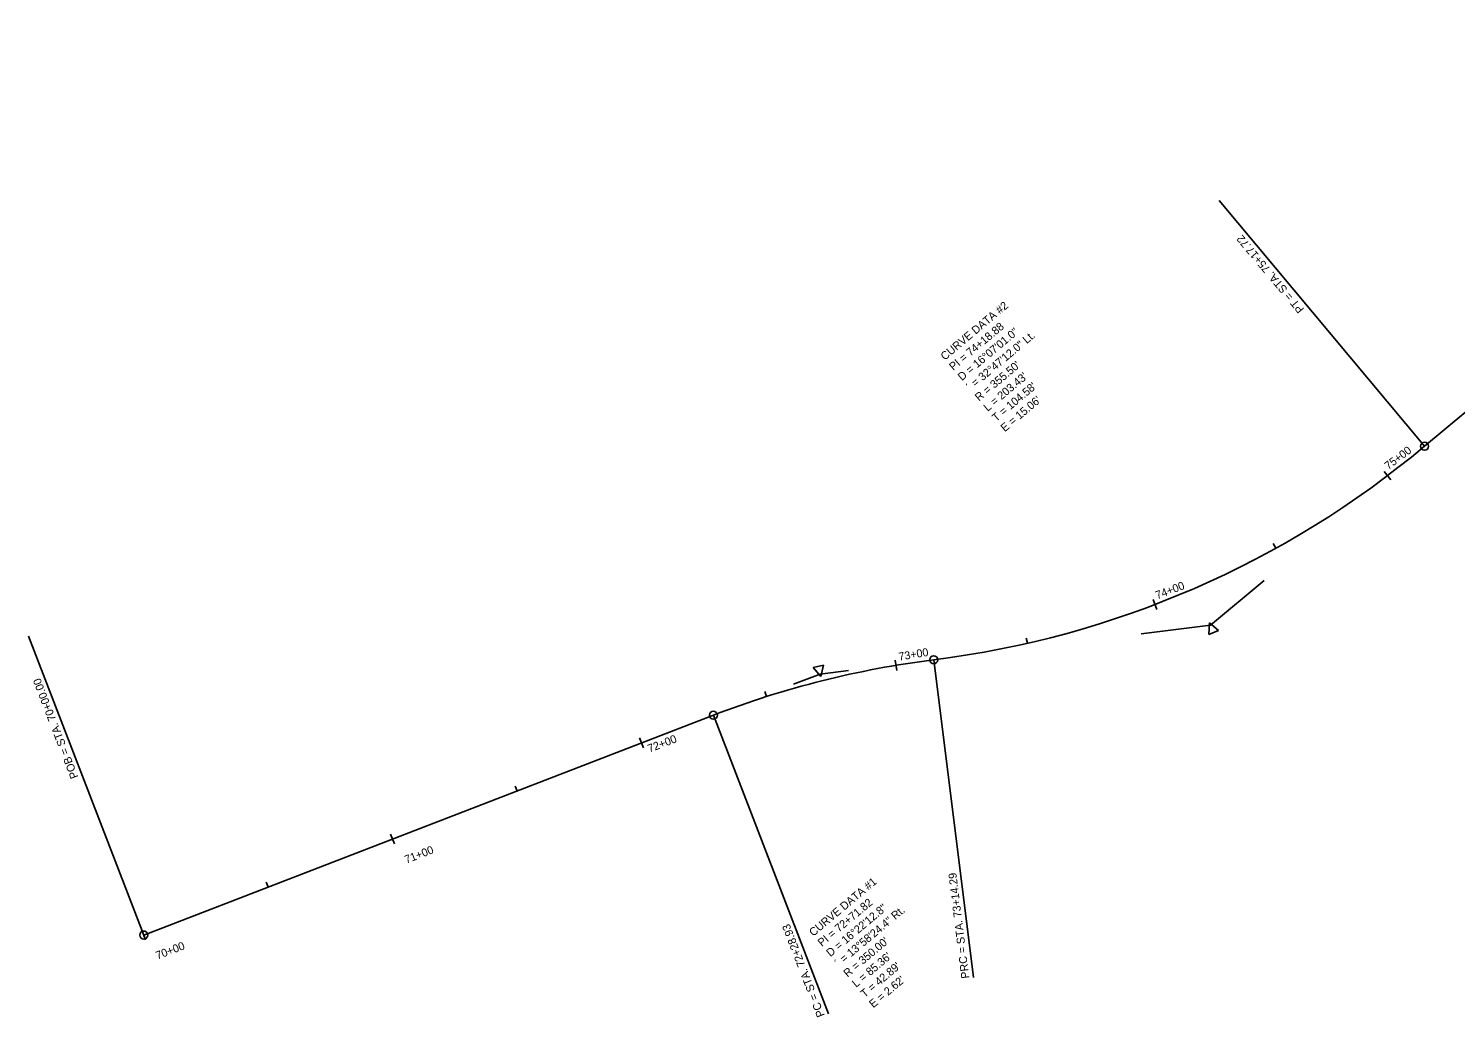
# Model space of a CAD drawing. Extents: x 939026 to 940035, y 627480 to 628252.
# Drawn here: x 939026 to 939561, y 627480 to 627851 of the extents above; entities that cross this region are included whole.
import ezdxf

# ---------------------------------------------------------------- set-up
doc = ezdxf.new("R2010")
doc.units = 0
for name, color, linetype in [('D_Roadway_Centerline', 7, 'Continuous'), ('D_Roadway_Centerline_CurveData', 7, 'Continuous'), ('D_Roadway_Centerline_Flags', 7, 'Continuous'), ('D_Roadway_Centerline_Text', 7, 'Continuous')]:
    doc.layers.add(name, color=color, linetype=linetype)

msp = doc.modelspace()

# ---------------------------------------------------------------- linework, layer by layer
at = {"layer": 'D_Roadway_Centerline'}
for p, q in [((939549.37, 627694.24), (939736.56, 627850.77)), ((939069.18, 627511.07), (939282.77, 627593.45))]:
    msp.add_line(p, q, dxfattribs=at)
for centre, radius, start, end in [((939321.32, 627966.96), 355.5, 277.1159, 309.9025), ((939408.71, 627266.89), 350, 97.1159, 111.0893)]:
    msp.add_arc(centre, radius, start, end, dxfattribs=at)
at = {"layer": 'D_Roadway_Centerline_CurveData'}
for p, q in [((939468.51, 627623.66), (939468.74, 627628.06)), ((939468.74, 627628.06), (939472.12, 627625.23)), ((939468.74, 627628.06), (939469.13, 627627.15)), ((939472.12, 627625.23), (939468.51, 627623.66)), ((939320.17, 627611.27), (939323.98, 627612.23)), ((939323.03, 627607.93), (939320.17, 627611.27)), ((939323.98, 627612.23), (939323.03, 627607.93)), ((939323.03, 627607.93), (939322.79, 627608.88))]:
    msp.add_line(p, q, dxfattribs=at)
for points in [[(939443.19, 627623.91), (939469.13, 627627.15), (939489.19, 627643.92)], [(939312.79, 627605.03), (939322.79, 627608.88), (939333.43, 627610.21)]]:
    msp.add_lwpolyline(points, dxfattribs=at)
at = {"layer": 'D_Roadway_Centerline_Flags'}
for points in [[(939549.37, 627694.24), (939472.39, 627786.3)], [(939069.18, 627511.07), (939026, 627623.04)], [(939365.36, 627614.2), (939380.22, 627495.12)], [(939282.77, 627593.45), (939325.95, 627481.49)]]:
    msp.add_lwpolyline(points, dxfattribs=at)
for centre in [(939549.37, 627694.24), (939365.36, 627614.2), (939282.77, 627593.45), (939069.18, 627511.07)]:
    msp.add_circle(centre, 1.5, dxfattribs=at)
at = {"layer": 'D_Roadway_Centerline_Text'}
for points in [[(939534.29, 627684.81), (939536.7, 627681.62)], [(939492.63, 627657.74), (939493.6, 627656)], [(939447.6, 627636.78), (939449.02, 627633.05)], [(939400.06, 627622.34), (939400.51, 627620.39)], [(939350.89, 627614.11), (939351.54, 627610.16)], [(939302.04, 627602.34), (939302.65, 627600.43)], [(939255.06, 627584.91), (939256.5, 627581.17)], [(939208.41, 627566.91), (939209.13, 627565.05)], [(939161.76, 627548.92), (939163.2, 627545.19)], [(939115.11, 627530.93), (939115.83, 627529.07)], [(939068.46, 627512.94), (939069.9, 627509.21)]]:
    msp.add_lwpolyline(points, dxfattribs=at)

# ---------------------------------------------------------------- texts
at = {"layer": 'D_Roadway_Centerline_CurveData'}
for s, rotation, p in [('CURVE DATA #2', 40.0101, (939369.49, 627726.26)), ('PI = 74+18.88', 40.0101, (939372.7, 627722.43)), ('D = 16%%d07\'01.0"', 40.0101, (939375.92, 627718.6)), ('´ = 32%%d47\'12.0" Lt.', 40.0101, (939379.13, 627714.77)), ("R = 355.50'", 40.0101, (939382.34, 627710.94)), ("L = 203.43'", 40.0101, (939385.56, 627707.11)), ("T = 104.58'", 40.0101, (939388.77, 627703.28)), ("E = 15.06'", 40.0101, (939391.99, 627699.45)), ('CURVE DATA #1', 39.9833, (939320.2, 627510.4)), ('PI = 72+71.82', 39.9833, (939323.41, 627506.57)), ('D = 16%%d22\'12.8"', 39.9833, (939326.62, 627502.74)), ('´ = 13%%d58\'24.4" Rt.', 39.9833, (939329.83, 627498.91)), ("R = 350.00'", 39.9833, (939333.05, 627495.08)), ("L = 85.36'", 39.9833, (939336.26, 627491.25)), ("T = 42.89'", 39.9833, (939339.47, 627487.41)), ("E = 2.62'", 39.9833, (939342.69, 627483.58))]:
    msp.add_text(s, height=3, rotation=rotation, dxfattribs=at).set_placement(p)
at = {"layer": 'D_Roadway_Centerline_Flags'}
for s, rotation, p in [('PT = STA. 75+17.72', 129.9025, (939504.4, 627745.67)), ('POB = STA. 70+00.00', 111.0893, (939044.72, 627570.33)), ('PRC = STA. 73+14.29', 97.1159, (939378.73, 627494.94)), ('PC = STA. 72+28.93', 111.0893, (939324.55, 627480.95))]:
    msp.add_text(s, height=3, rotation=rotation, dxfattribs=at).set_placement(p)
at = {"layer": 'D_Roadway_Centerline_Text'}
for s, rotation, p in [('75+00', 37.0465, (939535.79, 627685.32)), ('74+00', 20.9295, (939449.17, 627636.85)), ('73+00', 9.4554, (939352.45, 627613.86)), ('72+00', 21.0893, (939258.8, 627579.38)), ('71+00', 21.0893, (939167.66, 627537.8)), ('70+00', 21.0893, (939074.35, 627501.82))]:
    msp.add_text(s, height=3, rotation=rotation, dxfattribs=at).set_placement(p)

doc.saveas('drawing.dxf')
